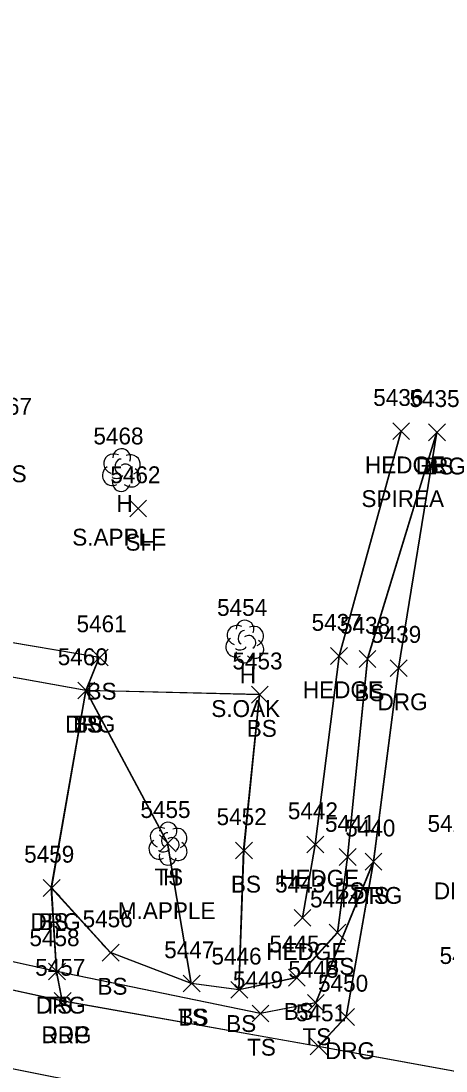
# Model space of a CAD drawing. Extents: x 1554668 to 1563881, y 831386 to 834374.
# Drawn here: x 1561902.3 to 1561952.8, y 833083.7 to 833208.3 of the extents above; entities that cross this region are included whole.
import ezdxf

# ---------------------------------------------------------------- set-up
doc = ezdxf.new("R2010")
doc.units = 0
for name, color, linetype in [('L_A', 7, 'Continuous'), ('L_C', 7, 'Continuous'), ('L_I', 7, 'Continuous'), ('L_TIC', 7, 'Continuous'), ('LAHR', 7, 'Continuous'), ('LELB', 7, 'Continuous'), ('LTD', 7, 'Continuous'), ('P_A', 7, 'Continuous'), ('P_I', 7, 'Continuous'), ('P_TIC', 7, 'Continuous'), ('PET', 7, 'Continuous'), ('PRC', 7, 'Continuous'), ('R_A', 7, 'Continuous'), ('R_I', 7, 'Continuous'), ('R_TIC', 7, 'Continuous'), ('RDG', 7, 'Continuous')]:
    doc.layers.add(name, color=color, linetype=linetype)

msp = doc.modelspace()

# ---------------------------------------------------------------- linework, layer by layer
at = {"layer": 'L_TIC'}
for points in [[(1561946.47, 833158.63), (1561948.47, 833160.63)], [(1561948.47, 833158.63), (1561946.47, 833160.63)], [(1561950.71, 833158.5), (1561952.71, 833160.5)], [(1561952.71, 833158.5), (1561950.71, 833160.5)], [(1561915.26, 833149.46), (1561917.26, 833151.46)], [(1561917.26, 833149.46), (1561915.26, 833151.46)], [(1561910.68, 833131.78), (1561912.68, 833133.78)], [(1561912.68, 833131.78), (1561910.68, 833133.78)], [(1561939.1, 833131.95), (1561941.1, 833133.95)], [(1561941.1, 833131.95), (1561939.1, 833133.95)], [(1561942.47, 833131.6), (1561944.47, 833133.6)], [(1561944.47, 833131.6), (1561942.47, 833133.6)], [(1561909.1, 833127.87), (1561911.1, 833129.87)], [(1561911.1, 833127.87), (1561909.1, 833129.87)], [(1561909.1, 833127.87), (1561911.1, 833129.87)], [(1561911.1, 833127.87), (1561909.1, 833129.87)], [(1561929.7, 833127.37), (1561931.7, 833129.37)], [(1561931.7, 833127.37), (1561929.7, 833129.37)], [(1561918.78, 833109.74), (1561920.78, 833111.74)], [(1561920.78, 833109.74), (1561918.78, 833111.74)], [(1561936.28, 833109.59), (1561938.28, 833111.59)], [(1561938.28, 833109.59), (1561936.28, 833111.59)], [(1561927.82, 833108.89), (1561929.82, 833110.89)], [(1561929.82, 833108.89), (1561927.82, 833110.89)], [(1561940.11, 833108.1), (1561942.11, 833110.1)], [(1561942.11, 833108.1), (1561940.11, 833110.1)], [(1561943.18, 833107.55), (1561945.18, 833109.55)], [(1561945.18, 833107.55), (1561943.18, 833109.55)], [(1561904.99, 833104.44), (1561906.99, 833106.44)], [(1561906.99, 833104.44), (1561904.99, 833106.44)], [(1561934.76, 833100.89), (1561936.76, 833102.89)], [(1561936.76, 833100.89), (1561934.76, 833102.89)], [(1561938.91, 833099.13), (1561940.91, 833101.13)], [(1561940.91, 833099.13), (1561938.91, 833101.13)], [(1561911.98, 833096.77), (1561913.98, 833098.77)], [(1561913.98, 833096.77), (1561911.98, 833098.77)], [(1561905.61, 833094.53), (1561907.61, 833096.53)], [(1561907.61, 833094.53), (1561905.61, 833096.53)], [(1561921.6, 833093.1), (1561923.6, 833095.1)], [(1561923.6, 833093.1), (1561921.6, 833095.1)], [(1561921.6, 833093.1), (1561923.6, 833095.1)], [(1561923.6, 833093.1), (1561921.6, 833095.1)], [(1561934.09, 833093.79), (1561936.09, 833095.79)], [(1561936.09, 833093.79), (1561934.09, 833095.79)], [(1561927.26, 833092.35), (1561929.26, 833094.35)], [(1561929.26, 833092.35), (1561927.26, 833094.35)], [(1561927.26, 833092.35), (1561929.26, 833094.35)], [(1561929.26, 833092.35), (1561927.26, 833094.35)], [(1561936.34, 833090.79), (1561938.34, 833092.79)], [(1561938.34, 833090.79), (1561936.34, 833092.79)], [(1561929.77, 833089.54), (1561931.77, 833091.54)], [(1561931.77, 833089.54), (1561929.77, 833091.54)]]:
    msp.add_lwpolyline(points, dxfattribs=at)
at = {"layer": 'LAHR'}
for points in [[(1561947.42, 833159.64), (1561940.05, 833132.95), (1561937.23, 833110.6), (1561935.71, 833101.89)], [(1561947.42, 833159.64), (1561940.05, 833132.95), (1561937.23, 833110.6), (1561935.71, 833101.89)], [(1561947.42, 833159.64), (1561940.05, 833132.95), (1561937.23, 833110.6), (1561935.71, 833101.89)], [(1561947.47, 833159.63), (1561940.1, 833132.95), (1561937.28, 833110.59), (1561935.76, 833101.89)]]:
    msp.add_lwpolyline(points, dxfattribs=at)
at = {"layer": 'LELB'}
for points in [[(1561928.22, 833093.36), (1561928.77, 833109.9), (1561930.65, 833128.38), (1561910.05, 833128.88), (1561911.63, 833132.78), (1561898.48, 833135.01), (1561900.96, 833158.58)], [(1561928.22, 833093.36), (1561928.77, 833109.9), (1561930.65, 833128.38), (1561910.05, 833128.88), (1561911.63, 833132.78), (1561898.48, 833135.01), (1561900.96, 833158.58)], [(1561928.22, 833093.36), (1561928.77, 833109.9), (1561930.65, 833128.38), (1561910.05, 833128.88), (1561911.63, 833132.78), (1561898.48, 833135.01), (1561900.96, 833158.58)], [(1561928.26, 833093.35), (1561928.82, 833109.89), (1561930.7, 833128.37), (1561910.1, 833128.87), (1561911.68, 833132.78), (1561898.52, 833135), (1561901.01, 833158.58)], [(1561951.66, 833159.51), (1561943.42, 833132.61), (1561941.06, 833109.11), (1561939.86, 833100.14), (1561935.04, 833094.8), (1561928.22, 833093.36), (1561922.55, 833094.11), (1561912.93, 833097.78), (1561905.94, 833105.45)], [(1561951.66, 833159.51), (1561943.42, 833132.61), (1561941.06, 833109.11), (1561939.86, 833100.14), (1561935.04, 833094.8), (1561928.22, 833093.36), (1561922.55, 833094.11), (1561912.93, 833097.78), (1561905.94, 833105.45)], [(1561951.66, 833159.51), (1561943.42, 833132.61), (1561941.06, 833109.11), (1561939.86, 833100.14), (1561935.04, 833094.8), (1561928.22, 833093.36), (1561922.55, 833094.11), (1561912.93, 833097.78), (1561905.94, 833105.45)], [(1561951.71, 833159.5), (1561943.47, 833132.6), (1561941.11, 833109.1), (1561939.91, 833100.13), (1561935.09, 833094.79), (1561928.26, 833093.35), (1561922.6, 833094.1), (1561912.98, 833097.77), (1561905.99, 833105.44)], [(1561944.14, 833108.57), (1561937.29, 833091.8), (1561930.72, 833090.55), (1561906.56, 833095.54), (1561892, 833098.72), (1561885.65, 833099.05), (1561845.94, 833108.05), (1561842.64, 833114.69), (1561844.08, 833135.43)], [(1561944.14, 833108.57), (1561937.29, 833091.8), (1561930.72, 833090.55), (1561906.56, 833095.54), (1561892, 833098.72), (1561885.65, 833099.05), (1561845.94, 833108.05), (1561842.64, 833114.69), (1561844.08, 833135.43)], [(1561944.14, 833108.57), (1561937.29, 833091.8), (1561930.72, 833090.55), (1561906.56, 833095.54), (1561892, 833098.72), (1561885.65, 833099.05), (1561845.94, 833108.05), (1561842.64, 833114.69), (1561844.08, 833135.43)], [(1561944.18, 833108.55), (1561937.34, 833091.79), (1561930.77, 833090.54), (1561906.61, 833095.53), (1561892.05, 833098.71), (1561885.69, 833099.04), (1561845.99, 833108.04), (1561842.69, 833114.68), (1561844.13, 833135.42)], [(1561922.55, 833094.11), (1561919.73, 833110.75), (1561910.05, 833128.88)], [(1561922.55, 833094.11), (1561919.73, 833110.75), (1561910.05, 833128.88)], [(1561922.55, 833094.11), (1561919.73, 833110.75), (1561910.05, 833128.88)], [(1561922.6, 833094.1), (1561919.78, 833110.74), (1561910.1, 833128.87)]]:
    msp.add_lwpolyline(points, dxfattribs=at)
at = {"layer": 'LTD'}
for p, q in [((1561914.25, 833155.06), (1561914.25, 833155.06)), ((1561914.25, 833155.06), (1561914.25, 833155.06)), ((1561928.88, 833134.72), (1561928.88, 833134.72)), ((1561928.88, 833134.72), (1561928.88, 833134.72)), ((1561919.78, 833110.74), (1561919.78, 833110.74)), ((1561919.78, 833110.74), (1561919.78, 833110.74))]:
    msp.add_line(p, q, dxfattribs=at)
for centre in [(1561914.29, 833156.5), (1561928.93, 833136.15), (1561919.82, 833112.18)]:
    msp.add_arc(centre, 1.05, 335.5272, 180.9563, dxfattribs=at)
for centre, major_axis, ratio, start_param, end_param in [((1561913.45, 833155.73), (1.21, -0.51), 0.895232, 1.570796, 4.712389), ((1561914.04, 833155.52), (-0.208, -0.792), 0.645439, 3.141593, 6.283185), ((1561915.29, 833155.65), (-1.14, -0.48), 0.949671, 1.570796, 4.712389), ((1561913.16, 833154.35), (0.58, -1.04), 0.959034, 3.141593, 6.283185), ((1561914.75, 833154.9), (-0.5, 0.667), 0.989748, 3.141593, 6.283185), ((1561915.25, 833154.23), (-1.09, 0.79), 0.841452, 1.570796, 4.712389), ((1561914.25, 833153.56), (0.26, 1.06), 0.942809, 1.570796, 4.712389), ((1561913.79, 833154.31), (-0.625, -0.083), 0.423636, 0, 3.141593), ((1561928.09, 833135.39), (1.21, -0.51), 0.895232, 1.570796, 4.712389), ((1561928.67, 833135.18), (-0.208, -0.792), 0.645439, 3.141593, 6.283185), ((1561929.92, 833135.3), (-1.14, -0.48), 0.949671, 1.570796, 4.712389), ((1561927.8, 833134.01), (0.58, -1.04), 0.959034, 3.141593, 6.283185), ((1561929.38, 833134.55), (-0.5, 0.667), 0.989748, 3.141593, 6.283185), ((1561929.88, 833133.89), (-1.09, 0.79), 0.841452, 1.570796, 4.712389), ((1561928.88, 833133.22), (0.26, 1.06), 0.942809, 1.570796, 4.712389), ((1561928.42, 833133.97), (-0.625, -0.083), 0.423636, 0, 3.141593), ((1561918.98, 833111.41), (1.21, -0.51), 0.895232, 1.570796, 4.712389), ((1561920.82, 833111.33), (-1.14, -0.48), 0.949671, 1.570796, 4.712389), ((1561918.69, 833110.03), (0.58, -1.04), 0.959034, 3.141593, 6.283185), ((1561919.57, 833111.2), (-0.208, -0.792), 0.645439, 3.141593, 6.283185), ((1561920.28, 833110.58), (-0.5, 0.667), 0.989748, 3.141593, 6.283185), ((1561919.32, 833109.99), (-0.625, -0.083), 0.423636, 0, 3.141593), ((1561920.78, 833109.91), (-1.09, 0.79), 0.841452, 1.570796, 4.712389), ((1561919.78, 833109.24), (0.26, 1.06), 0.942809, 1.570796, 4.712389)]:
    msp.add_ellipse(centre, major_axis=major_axis, ratio=ratio, start_param=start_param, end_param=end_param, dxfattribs=at)
at = {"layer": 'P_TIC'}
for points in [[(1561906.29, 833091.02), (1561908.29, 833093.02)], [(1561908.29, 833091.02), (1561906.29, 833093.02)], [(1561936.67, 833085.62), (1561938.67, 833087.62)], [(1561938.67, 833085.62), (1561936.67, 833087.62)]]:
    msp.add_lwpolyline(points, dxfattribs=at)
at = {"layer": 'PET'}
for points in [[(1562141.25, 833047.12), (1562119.22, 833051.02), (1562082.19, 833058), (1562039.03, 833066.72), (1561990.71, 833076.46), (1561963.84, 833081.85), (1561937.62, 833086.63), (1561907.24, 833092.03), (1561888.37, 833096.12), (1561864.2, 833100.58), (1561845.91, 833105.22), (1561814.16, 833114.01), (1561794.69, 833124.47), (1561784.58, 833134.98), (1561776.4, 833149.04), (1561771.88, 833170.92), (1561772.45, 833192.58), (1561778.44, 833223.18)], [(1562141.25, 833047.12), (1562119.22, 833051.02), (1562082.19, 833058), (1562039.03, 833066.72), (1561990.71, 833076.46), (1561963.84, 833081.85), (1561937.62, 833086.63), (1561907.24, 833092.03), (1561888.37, 833096.12), (1561864.2, 833100.58), (1561845.91, 833105.22), (1561814.16, 833114.01), (1561794.69, 833124.47), (1561784.58, 833134.98), (1561776.4, 833149.04), (1561771.88, 833170.92), (1561772.45, 833192.58), (1561778.44, 833223.18)], [(1562141.25, 833047.12), (1562119.22, 833051.02), (1562082.19, 833058), (1562039.03, 833066.72), (1561990.71, 833076.46), (1561963.84, 833081.85), (1561937.62, 833086.63), (1561907.24, 833092.03), (1561888.37, 833096.12), (1561864.2, 833100.58), (1561845.91, 833105.22), (1561814.16, 833114.01), (1561794.69, 833124.47), (1561784.58, 833134.98), (1561776.4, 833149.04), (1561771.88, 833170.92), (1561772.45, 833192.58), (1561778.44, 833223.18)], [(1562141.25, 833047.12), (1562119.21, 833051.02), (1562082.18, 833058.01), (1562039.08, 833066.71), (1561990.76, 833076.45), (1561963.89, 833081.84), (1561937.67, 833086.62), (1561907.29, 833092.02), (1561888.41, 833096.12), (1561864.24, 833100.57), (1561845.95, 833105.21), (1561814.21, 833114), (1561794.69, 833124.47), (1561784.58, 833134.98), (1561776.4, 833149.05), (1561771.88, 833170.92), (1561772.45, 833192.58), (1561778.44, 833223.18)]]:
    msp.add_lwpolyline(points, dxfattribs=at)
at = {"layer": 'PRC'}
for points in [[(1562300.3, 833002.63), (1562265.06, 833007.76), (1562229.75, 833015.9), (1562188.56, 833027.16), (1562163.87, 833032.84), (1562128.37, 833039.75), (1562080.01, 833048.85), (1562037.12, 833057.38), (1561989.03, 833066.78), (1561944.7, 833075.35), (1561893.61, 833085.49), (1561855.76, 833092.69), (1561805.69, 833106.79), (1561782.45, 833121.4), (1561772.46, 833130.94), (1561764.81, 833144.51), (1561760.94, 833173.07), (1561763.81, 833193.36), (1561770.11, 833225.65), (1561775.84, 833254.58), (1561787.63, 833309.04), (1561795.14, 833348.53), (1561800.21, 833371.54), (1561806.44, 833405.19)], [(1562300.3, 833002.63), (1562265.06, 833007.76), (1562229.75, 833015.9), (1562188.56, 833027.16), (1562163.87, 833032.84), (1562128.37, 833039.75), (1562080.01, 833048.85), (1562037.12, 833057.38), (1561989.03, 833066.78), (1561944.7, 833075.35), (1561893.61, 833085.49), (1561855.76, 833092.69), (1561805.69, 833106.79), (1561782.45, 833121.4), (1561772.46, 833130.94), (1561764.81, 833144.51), (1561760.94, 833173.07), (1561763.81, 833193.36), (1561770.11, 833225.65), (1561775.84, 833254.58), (1561787.63, 833309.04), (1561795.14, 833348.53), (1561800.21, 833371.54), (1561806.44, 833405.19)], [(1562300.3, 833002.63), (1562265.06, 833007.76), (1562229.75, 833015.9), (1562188.56, 833027.16), (1562163.87, 833032.84), (1562128.37, 833039.75), (1562080.01, 833048.85), (1562037.12, 833057.38), (1561989.03, 833066.78), (1561944.7, 833075.35), (1561893.61, 833085.49), (1561855.76, 833092.69), (1561805.69, 833106.79), (1561782.45, 833121.4), (1561772.46, 833130.94), (1561764.81, 833144.51), (1561760.94, 833173.07), (1561763.81, 833193.36), (1561770.11, 833225.65), (1561775.84, 833254.58), (1561787.63, 833309.04), (1561795.14, 833348.53), (1561800.21, 833371.54), (1561806.44, 833405.19)], [(1562300.29, 833002.64), (1562265.06, 833007.76), (1562229.75, 833015.9), (1562188.56, 833027.16), (1562163.87, 833032.83), (1562128.37, 833039.74), (1562080.01, 833048.85), (1562037.17, 833057.37), (1561989.08, 833066.77), (1561944.75, 833075.34), (1561893.66, 833085.49), (1561855.8, 833092.68), (1561805.74, 833106.78), (1561782.44, 833121.4), (1561772.46, 833130.94), (1561764.82, 833144.51), (1561760.94, 833173.07), (1561763.81, 833193.36), (1561770.11, 833225.66), (1561775.83, 833254.58), (1561787.63, 833309.04), (1561795.14, 833348.54), (1561800.21, 833371.54), (1561806.44, 833405.19)]]:
    msp.add_lwpolyline(points, dxfattribs=at)
at = {"layer": 'R_TIC'}
for points in [[(1561950.71, 833158.5), (1561952.71, 833160.5)], [(1561952.71, 833158.5), (1561950.71, 833160.5)], [(1561946.17, 833130.52), (1561948.17, 833132.52)], [(1561948.17, 833130.52), (1561946.17, 833132.52)], [(1561909.1, 833127.87), (1561911.1, 833129.87)], [(1561911.1, 833127.87), (1561909.1, 833129.87)], [(1561943.18, 833107.55), (1561945.18, 833109.55)], [(1561945.18, 833107.55), (1561943.18, 833109.55)], [(1561904.99, 833104.44), (1561906.99, 833106.44)], [(1561906.99, 833104.44), (1561904.99, 833106.44)], [(1561905.61, 833094.53), (1561907.61, 833096.53)], [(1561907.61, 833094.53), (1561905.61, 833096.53)], [(1561906.29, 833091.02), (1561908.29, 833093.02)], [(1561908.29, 833091.02), (1561906.29, 833093.02)], [(1561939.94, 833089.13), (1561941.94, 833091.13)], [(1561941.94, 833089.13), (1561939.94, 833091.13)], [(1561936.67, 833085.62), (1561938.67, 833087.62)], [(1561938.67, 833085.62), (1561936.67, 833087.62)]]:
    msp.add_lwpolyline(points, dxfattribs=at)
at = {"layer": 'RDG'}
for points in [[(1561951.66, 833159.51), (1561947.12, 833131.53), (1561944.14, 833108.57), (1561940.9, 833090.14), (1561937.62, 833086.63)], [(1561951.66, 833159.51), (1561947.12, 833131.53), (1561944.14, 833108.57), (1561940.9, 833090.14), (1561937.62, 833086.63)], [(1561951.66, 833159.51), (1561947.12, 833131.53), (1561944.14, 833108.57), (1561940.9, 833090.14), (1561937.62, 833086.63)], [(1561951.71, 833159.5), (1561947.17, 833131.52), (1561944.18, 833108.55), (1561940.94, 833090.13), (1561937.67, 833086.62)], [(1561907.24, 833092.03), (1561906.56, 833095.54), (1561905.94, 833105.45), (1561910.05, 833128.88), (1561898.14, 833131), (1561896.6, 833123.69), (1561896.16, 833110.53), (1561892, 833098.72), (1561888.37, 833096.12)], [(1561907.24, 833092.03), (1561906.56, 833095.54), (1561905.94, 833105.45), (1561910.05, 833128.88), (1561898.14, 833131), (1561896.6, 833123.69), (1561896.16, 833110.53), (1561892, 833098.72), (1561888.37, 833096.12)], [(1561907.24, 833092.03), (1561906.56, 833095.54), (1561905.94, 833105.45), (1561910.05, 833128.88), (1561898.14, 833131), (1561896.6, 833123.69), (1561896.16, 833110.53), (1561892, 833098.72), (1561888.37, 833096.12)], [(1561907.29, 833092.02), (1561906.61, 833095.53), (1561905.99, 833105.44), (1561910.1, 833128.87), (1561898.19, 833130.99), (1561896.65, 833123.68), (1561896.2, 833110.52), (1561892.05, 833098.71), (1561888.41, 833096.12)]]:
    msp.add_lwpolyline(points, dxfattribs=at)

# ---------------------------------------------------------------- texts
at = {"layer": 'L_A'}
for s, p in [('HEDGE', (1561943.17, 833154.63)), ('BS', (1561950.15, 833154.5)), ('BS', (1561899.45, 833153.58)), ('H', (1561913.68, 833150.06)), ('SH', (1561914.75, 833145.46)), ('H', (1561928.31, 833129.72)), ('BS', (1561910.12, 833127.78)), ('HEDGE', (1561935.8, 833127.95)), ('BS', (1561941.91, 833127.6)), ('TS', (1561908.51, 833123.87)), ('BS', (1561908.54, 833123.87)), ('BS', (1561929.14, 833123.37)), ('TS', (1561918.18, 833105.74)), ('H', (1561919.21, 833105.74)), ('HEDGE', (1561932.98, 833105.59)), ('BS', (1561927.26, 833104.89)), ('BS', (1561939.55, 833104.1)), ('TS', (1561942.59, 833103.55)), ('BS', (1561904.43, 833100.44)), ('HEDGE', (1561931.46, 833096.89)), ('BS', (1561938.35, 833095.13)), ('BS', (1561911.42, 833092.77)), ('TS', (1561905.02, 833090.53)), ('TS', (1561921.01, 833089.1)), ('BS', (1561921.04, 833089.1)), ('BS', (1561933.53, 833089.79)), ('BS', (1561926.7, 833088.35)), ('BS', (1561926.7, 833088.35)), ('TS', (1561935.75, 833086.79)), ('TS', (1561929.18, 833085.54))]:
    msp.add_text(s, height=2, dxfattribs=at).set_placement(p)
at = {"layer": 'L_C'}
for s, p in [('SPIREA', (1561942.75, 833150.63)), ('S.APPLE', (1561908.43, 833146.06)), ('S.OAK', (1561924.93, 833125.72)), ('M.APPLE', (1561913.84, 833101.74))]:
    msp.add_text(s, height=2, dxfattribs=at).set_placement(p)
at = {"layer": 'L_I'}
for s, p in [('5436', (1561944.15, 833162.63)), ('5467', (1561897.7, 833161.58)), ('5435', (1561948.45, 833162.5)), ('5468', (1561910.94, 833158.06)), ('5462', (1561912.95, 833153.46)), ('5454', (1561925.62, 833137.72)), ('5461', (1561908.94, 833135.78)), ('5437', (1561936.84, 833135.95)), ('5438', (1561940.21, 833135.6)), ('5460', (1561906.71, 833131.87)), ('5460', (1561906.71, 833131.87)), ('5453', (1561927.44, 833131.37)), ('5455', (1561916.52, 833113.74)), ('5455', (1561916.52, 833113.74)), ('5452', (1561925.56, 833112.89)), ('5442', (1561934.02, 833113.59)), ('5441', (1561938.42, 833112.1)), ('5440', (1561940.83, 833111.55)), ('5459', (1561902.72, 833108.44)), ('5443', (1561932.5, 833104.89)), ('5444', (1561936.65, 833103.13)), ('5456', (1561909.66, 833100.77)), ('5458', (1561903.35, 833098.53)), ('5445', (1561931.83, 833097.79)), ('5447', (1561919.34, 833097.1)), ('5447', (1561919.34, 833097.1)), ('5446', (1561924.95, 833096.35)), ('5446', (1561924.95, 833096.35)), ('5448', (1561934.08, 833094.79)), ('5449', (1561927.5, 833093.54))]:
    msp.add_text(s, height=2, dxfattribs=at).set_placement(p)
at = {"layer": 'P_A'}
msp.add_text('RDP', height=2, dxfattribs=at).set_placement((1561904.77, 833087.02))
at = {"layer": 'P_I'}
for s, p in [('5457', (1561904.03, 833095.02)), ('5451', (1561934.98, 833089.62))]:
    msp.add_text(s, height=2, dxfattribs=at).set_placement(p)
at = {"layer": 'R_A'}
for p in [(1561949.2, 833154.5), (1561944.66, 833126.52), (1561907.59, 833123.87), (1561951.35, 833104.09), (1561941.67, 833103.55), (1561903.48, 833100.44), (1561904.1, 833090.53), (1561904.77, 833087.02), (1561938.43, 833085.13)]:
    msp.add_text('DRG', height=2, dxfattribs=at).set_placement(p)
at = {"layer": 'R_I'}
for s, p in [('5435', (1561948.45, 833162.5)), ('5439', (1561943.9, 833134.52)), ('5460', (1561906.71, 833131.87)), ('5440', (1561940.83, 833111.55)), ('5429', (1561950.6, 833112.09)), ('5459', (1561902.72, 833108.44)), ('5458', (1561903.35, 833098.53)), ('5425', (1561952.03, 833096.42)), ('5457', (1561904.03, 833095.02)), ('5450', (1561937.6, 833093.13)), ('5451', (1561934.98, 833089.62))]:
    msp.add_text(s, height=2, dxfattribs=at).set_placement(p)

doc.saveas('drawing.dxf')
